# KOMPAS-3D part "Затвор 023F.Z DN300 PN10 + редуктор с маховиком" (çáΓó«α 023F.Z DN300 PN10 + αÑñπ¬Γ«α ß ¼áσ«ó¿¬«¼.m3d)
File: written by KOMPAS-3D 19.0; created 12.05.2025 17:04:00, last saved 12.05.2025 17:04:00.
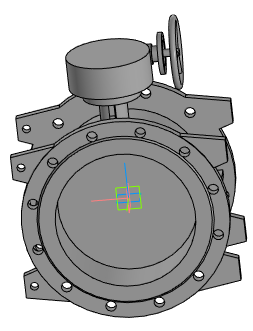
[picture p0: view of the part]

Document properties: Полное имя файла: Затвор 023F.Z DN300 PN10 + редуктор с маховиком.a3d

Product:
- Part/product: Затвор 023F.Z DN300 PN10 + редуктор с маховиком
    Масса: 97.8296

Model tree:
1. Операция без истории:1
